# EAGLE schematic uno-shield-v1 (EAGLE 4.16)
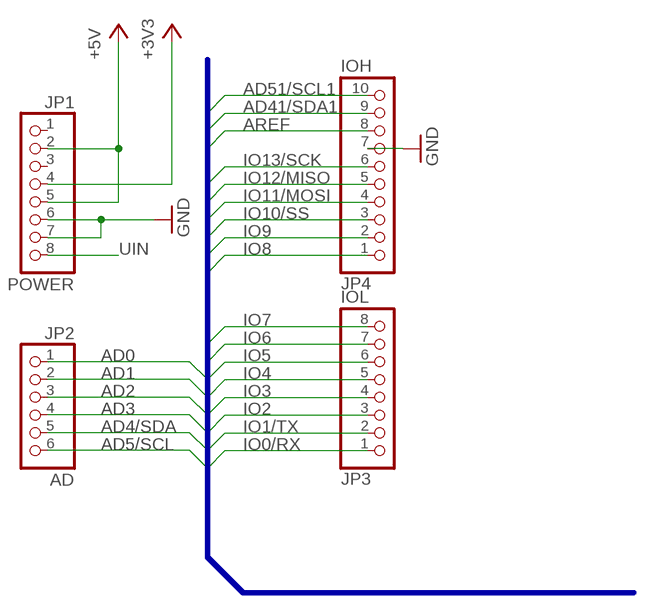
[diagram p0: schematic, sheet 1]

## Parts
JP1  POWER  PINHD-1X8  [1X08]
JP2  AD  PINHD-1X6  [1X06]
JP3  IOL  PINHD-1X8  [1X08]
JP4  IOH  PINHD-1X10  [1X10]

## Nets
+3V3: JP1.4
+5V: JP1.2 JP1.5
AD0: JP2.1
AD1: JP2.2
AD2: JP2.3
AD3: JP2.4
AD4/SDA: JP2.5
AD5/SCL: JP2.6
AD41/SDA1: JP4.9
AD51/SCL1: JP4.10
AREF: JP4.8
GND: JP1.6 JP1.7 JP4.7
IO0/RX: JP3.1
IO1/TX: JP3.2
IO2: JP3.3
IO3: JP3.4
IO4: JP3.5
IO5: JP3.6
IO6: JP3.7
IO7: JP3.8
IO8: JP4.1
IO9: JP4.2
IO10/SS: JP4.3
IO11/MOSI: JP4.4
IO12/MISO: JP4.5
IO13/SCK: JP4.6
UIN: JP1.8
Unconnected: JP1.1 JP1.3

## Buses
RESET,AD0,AD1,AD2,AD3,AD4/SDA,AD5/SCL,IO0/RX,IO1/TX,IO2,IO3,IO4,IO5,IO6,IO7,IO8,IO9,IO10/SS,IO11/MOSI,IO12/MISO,IO13/SCK,AREF,AD41/SDA1,AD51/SCL1

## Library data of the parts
JP1 JP3 = pinhead:PINHD-1X8: PIN HEADER
JP2 = pinhead:PINHD-1X6: PIN HEADER
JP4 = pinhead:PINHD-1X10: PIN HEADER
